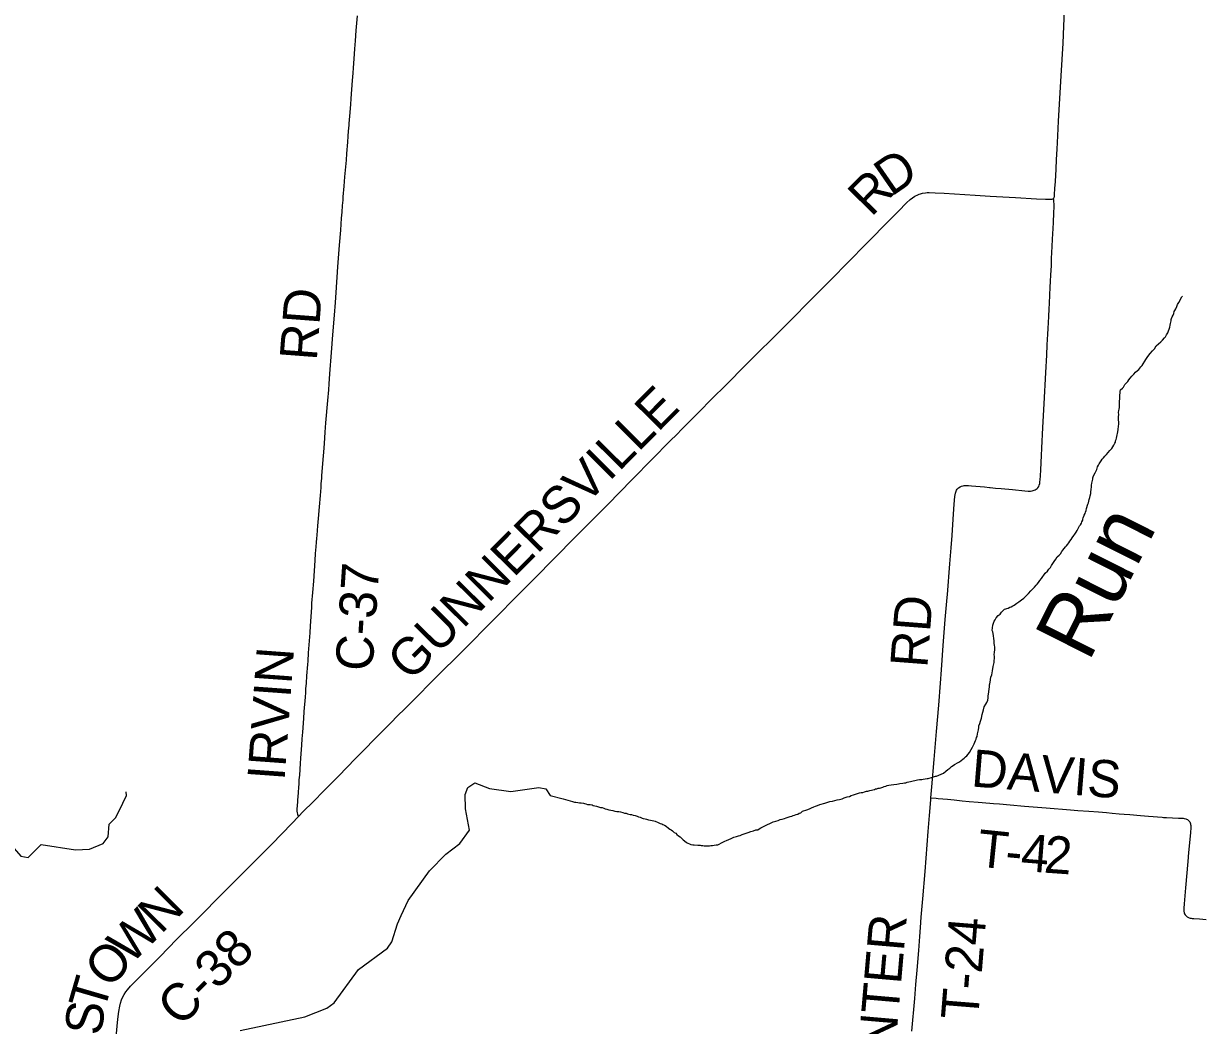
# Model space of a CAD drawing. Extents: x -49 to -8.2, y 9.4 to 23.5.
# Drawn here: x -45.157 to -44.259, y 16.399 to 17.164 of the extents above; entities that cross this region are included whole.
import ezdxf

# ---------------------------------------------------------------- set-up
doc = ezdxf.new("R2010")
doc.units = 0
for name, color, linetype in [('GM_X_County_Road', 7, 'Continuous'), ('GM_X_County_Road_Text', 7, 'Continuous'), ('GM_X_Minor_River', 7, 'Continuous'), ('GM_X_Minor_River_Text', 7, 'Continuous'), ('GM_X_Township_Road', 7, 'Continuous'), ('GM_X_Township_Road_Text', 7, 'Continuous')]:
    doc.layers.add(name, color=color, linetype=linetype)

msp = doc.modelspace()

# ---------------------------------------------------------------- linework, layer by layer
at = {"layer": 'GM_X_County_Road'}
for points in [[(-44.37073, 17.03015), (-44.37057, 17.03029), (-44.37036, 17.03061), (-44.37019, 17.03103), (-44.37007, 17.03142), (-44.36999, 17.03185), (-44.36994, 17.03249), (-44.36989, 17.03307), (-44.36958, 17.03784), (-44.36928, 17.04311), (-44.36878, 17.05241), (-44.36842, 17.05986), (-44.36804, 17.06761), (-44.36754, 17.07785), (-44.36692, 17.08902), (-44.3664, 17.0977), (-44.36497, 17.12376), (-44.36345, 17.14857), (-44.36281, 17.1616), (-44.36196, 17.17898)], [(-44.94677, 16.55865), (-44.94719, 16.56018), (-44.94762, 16.56178), (-44.94776, 16.56239), (-44.94784, 16.56312), (-44.94776, 16.56478), (-44.94763, 16.5665), (-44.9473, 16.57047), (-44.94697, 16.57478), (-44.94686, 16.57601), (-44.9468, 16.57724), (-44.94655, 16.58094), (-44.94631, 16.58372), (-44.94612, 16.58682), (-44.94582, 16.59022), (-44.94521, 16.59921), (-44.94492, 16.60323), (-44.94413, 16.61314), (-44.94382, 16.6181), (-44.94342, 16.62306), (-44.94272, 16.6336), (-44.94232, 16.63886), (-44.94147, 16.6497), (-44.94121, 16.65341), (-44.94103, 16.6562), (-44.94066, 16.66053), (-44.94026, 16.6661), (-44.9396, 16.67477), (-44.93942, 16.67724), (-44.93903, 16.68348), (-44.93794, 16.69892), (-44.93758, 16.70425), (-44.93669, 16.71816), (-44.93645, 16.72157), (-44.93583, 16.72962), (-44.93513, 16.73829), (-44.93401, 16.75409), (-44.93368, 16.75936), (-44.93348, 16.76184), (-44.93326, 16.76431), (-44.93298, 16.76803), (-44.93273, 16.77081), (-44.93255, 16.77328), (-44.93196, 16.7804), (-44.93153, 16.78595), (-44.9308, 16.79493), (-44.93005, 16.8036), (-44.92981, 16.80669), (-44.92954, 16.80979), (-44.92936, 16.81257), (-44.92903, 16.81691), (-44.92895, 16.81845), (-44.92794, 16.83115), (-44.92752, 16.83673), (-44.92701, 16.84323), (-44.92629, 16.8519), (-44.92577, 16.85903), (-44.92439, 16.87606), (-44.92369, 16.88411), (-44.92331, 16.88875), (-44.92273, 16.89649), (-44.92153, 16.9126), (-44.92046, 16.92623), (-44.91933, 16.9411), (-44.91858, 16.9507), (-44.91798, 16.95845), (-44.91663, 16.97797), (-44.9154, 16.9944), (-44.91453, 17.00586), (-44.91422, 17.0105), (-44.91387, 17.01515), (-44.91351, 17.0198), (-44.9131, 17.02475), (-44.91278, 17.02877), (-44.91259, 17.03125), (-44.9119, 17.03961), (-44.91131, 17.04672), (-44.91023, 17.05941), (-44.90986, 17.06437), (-44.90918, 17.07304), (-44.90887, 17.07769), (-44.90855, 17.0814), (-44.9082, 17.08604), (-44.90809, 17.08728), (-44.90755, 17.09285), (-44.90682, 17.10183), (-44.90649, 17.10647), (-44.90544, 17.1201), (-44.90507, 17.12568), (-44.90477, 17.12971), (-44.90428, 17.13653), (-44.90369, 17.14428), (-44.90321, 17.15047), (-44.90265, 17.15822), (-44.90178, 17.1695)], [(-44.63127, 16.8772), (-44.62054, 16.88797), (-44.60569, 16.90299), (-44.57555, 16.93305), (-44.55189, 16.95684), (-44.53895, 16.96983), (-44.5289, 16.97999), (-44.51186, 16.99722), (-44.4971, 17.01233), (-44.48907, 17.02056), (-44.48292, 17.02675), (-44.48012, 17.02927), (-44.47838, 17.03062), (-44.47653, 17.03183), (-44.47427, 17.03299), (-44.47318, 17.03342), (-44.47219, 17.03376), (-44.47065, 17.03417), (-44.46845, 17.03454), (-44.46712, 17.03465), (-44.46561, 17.03465), (-44.46092, 17.03442), (-44.4541, 17.03408), (-44.43053, 17.03266), (-44.41906, 17.03199), (-44.39982, 17.03086), (-44.38363, 17.02988), (-44.37689, 17.0296), (-44.37259, 17.02961), (-44.37221, 17.02963), (-44.3717, 17.02969), (-44.3713, 17.02983), (-44.37084, 17.03005), (-44.37073, 17.03015)], [(-44.94677, 16.55865), (-44.94308, 16.56245), (-44.93563, 16.56995), (-44.92712, 16.57856), (-44.92255, 16.58322), (-44.91601, 16.58986), (-44.90992, 16.59607), (-44.90319, 16.60296), (-44.89751, 16.60871), (-44.88768, 16.61865), (-44.88095, 16.62553), (-44.87658, 16.62995), (-44.87091, 16.6357), (-44.86583, 16.64073), (-44.86273, 16.64378), (-44.85811, 16.64839), (-44.85373, 16.65278), (-44.84825, 16.6583), (-44.83556, 16.67109), (-44.82807, 16.67854), (-44.81358, 16.69304), (-44.80571, 16.70099), (-44.79631, 16.71049), (-44.79171, 16.71511), (-44.78469, 16.72215), (-44.77597, 16.731), (-44.76896, 16.73806), (-44.74908, 16.75816), (-44.73796, 16.76944), (-44.72966, 16.77784), (-44.72242, 16.78511), (-44.7108, 16.79677), (-44.69232, 16.81564), (-44.67648, 16.83188), (-44.66395, 16.84439), (-44.65737, 16.85098), (-44.65495, 16.8534), (-44.64137, 16.86706), (-44.63127, 16.8772)], [(-45.08591, 16.39077), (-45.08462, 16.40408), (-45.08387, 16.40995), (-45.08314, 16.41395), (-45.08251, 16.41639), (-45.08171, 16.41878), (-45.0807, 16.4211), (-45.07967, 16.42305), (-45.07847, 16.42492), (-45.07712, 16.42666), (-45.07481, 16.42922), (-45.06742, 16.4368), (-45.05247, 16.45172), (-45.03947, 16.46507), (-45.02698, 16.47764), (-45.01817, 16.4864), (-45.00944, 16.49524), (-45.00179, 16.50297), (-44.98725, 16.51743), (-44.96716, 16.53776), (-44.95195, 16.55331), (-44.94677, 16.55865)]]:
    msp.add_lwpolyline(points, dxfattribs=at)
at = {"layer": 'GM_X_Minor_River'}
for points in [[(-44.3141, 16.8906), (-44.31332, 16.89173), (-44.31234, 16.89304), (-44.31098, 16.89454), (-44.30942, 16.89623), (-44.30806, 16.89753), (-44.30652, 16.89884), (-44.30555, 16.89958), (-44.30477, 16.90071), (-44.30398, 16.90183), (-44.3032, 16.90277), (-44.30026, 16.90728), (-44.2987, 16.90954), (-44.29694, 16.91179), (-44.29519, 16.91385), (-44.29363, 16.91554), (-44.29245, 16.91761), (-44.29051, 16.91928), (-44.28896, 16.92078), (-44.2876, 16.92209), (-44.28605, 16.92377), (-44.28527, 16.92471), (-44.28448, 16.92602), (-44.2835, 16.92753), (-44.28309, 16.92904), (-44.28249, 16.93056), (-44.28208, 16.93188), (-44.28168, 16.9334), (-44.28146, 16.93472), (-44.28125, 16.93567), (-44.28085, 16.9368), (-44.28083, 16.93776), (-44.28062, 16.9387), (-44.28022, 16.93984), (-44.27944, 16.94116), (-44.27884, 16.94248), (-44.27862, 16.94381), (-44.27804, 16.94475), (-44.27744, 16.94607), (-44.27665, 16.94776), (-44.27605, 16.94928), (-44.27507, 16.95078), (-44.27289, 16.95512), (-44.27231, 16.95568), (-44.27231, 16.95549)], [(-44.36783, 16.75686), (-44.36647, 16.75816), (-44.3655, 16.7591), (-44.36432, 16.76098), (-44.36354, 16.76191), (-44.36257, 16.76304), (-44.36159, 16.76435), (-44.36081, 16.76529), (-44.35984, 16.76641), (-44.35905, 16.76754), (-44.35827, 16.76886), (-44.35729, 16.76998), (-44.35651, 16.7713), (-44.35533, 16.77299), (-44.35436, 16.77412), (-44.35338, 16.77562), (-44.35278, 16.77694), (-44.3518, 16.77845), (-44.35081, 16.78033), (-44.35003, 16.78127), (-44.34944, 16.78259), (-44.34904, 16.78353), (-44.34845, 16.78466), (-44.34824, 16.78561), (-44.34803, 16.78656), (-44.34763, 16.78769), (-44.34742, 16.78864), (-44.34664, 16.78996), (-44.34643, 16.79091), (-44.34583, 16.79223), (-44.34542, 16.79374), (-44.34441, 16.79696), (-44.34401, 16.7979), (-44.3438, 16.79923), (-44.34339, 16.80056), (-44.34298, 16.80207), (-44.34277, 16.8034), (-44.34235, 16.8051), (-44.34214, 16.80643), (-44.34192, 16.80814), (-44.34169, 16.81023), (-44.34166, 16.81156), (-44.34145, 16.81289), (-44.34124, 16.81403), (-44.34103, 16.81498), (-44.34082, 16.81592), (-44.34061, 16.81706), (-44.3402, 16.81858), (-44.33883, 16.82084), (-44.33842, 16.82197), (-44.33763, 16.82348), (-44.33742, 16.82442), (-44.33703, 16.82537), (-44.33643, 16.82669), (-44.33584, 16.82763), (-44.33544, 16.82857), (-44.33428, 16.82989), (-44.33348, 16.83139), (-44.33251, 16.83233), (-44.33154, 16.83364), (-44.33037, 16.83495), (-44.32901, 16.83626), (-44.32765, 16.83795), (-44.32628, 16.83944), (-44.3255, 16.84057), (-44.32471, 16.84208), (-44.32392, 16.8434), (-44.32334, 16.84434), (-44.32332, 16.84529), (-44.32292, 16.84623), (-44.32271, 16.84718), (-44.32231, 16.84851), (-44.32209, 16.84983), (-44.32188, 16.85078), (-44.32126, 16.85362), (-44.32143, 16.85458), (-44.32103, 16.85571), (-44.3212, 16.85667), (-44.32099, 16.85781), (-44.32077, 16.85932), (-44.32112, 16.86142), (-44.32108, 16.86352), (-44.32085, 16.86542), (-44.32101, 16.86694), (-44.3208, 16.86846), (-44.32059, 16.86941), (-44.32037, 16.87073), (-44.32035, 16.87207), (-44.32032, 16.87359), (-44.32029, 16.87549), (-44.32006, 16.87739), (-44.32022, 16.87892), (-44.32001, 16.88024), (-44.31998, 16.88158), (-44.31996, 16.88291), (-44.31956, 16.88404), (-44.3182, 16.88535), (-44.31742, 16.88629), (-44.31624, 16.88817), (-44.31488, 16.88966), (-44.3141, 16.8906)], [(-44.44621, 16.59844), (-44.44352, 16.59991), (-44.44255, 16.60047), (-44.43985, 16.60251), (-44.43888, 16.60325), (-44.43791, 16.60419), (-44.43694, 16.60512), (-44.43578, 16.60624), (-44.4348, 16.60756), (-44.43342, 16.60981), (-44.43263, 16.61151), (-44.43184, 16.61302), (-44.43125, 16.61415), (-44.43065, 16.61547), (-44.43025, 16.6168), (-44.42985, 16.61774), (-44.42945, 16.61888), (-44.42905, 16.61982), (-44.42863, 16.62172), (-44.42821, 16.6238), (-44.428, 16.62494), (-44.42778, 16.62665), (-44.42757, 16.62779), (-44.42696, 16.62968), (-44.42636, 16.63138), (-44.42615, 16.63233), (-44.42574, 16.63384), (-44.42512, 16.6365), (-44.42471, 16.6382), (-44.4241, 16.64009), (-44.42368, 16.64237), (-44.42231, 16.64444), (-44.42152, 16.64575), (-44.42092, 16.64745), (-44.4205, 16.64916), (-44.42048, 16.65049), (-44.42004, 16.65391), (-44.4198, 16.65619), (-44.41959, 16.65733), (-44.41956, 16.65904), (-44.41935, 16.65999), (-44.41914, 16.66113), (-44.41849, 16.66511), (-44.4177, 16.66681), (-44.41726, 16.66984), (-44.41663, 16.67326), (-44.41621, 16.67515), (-44.41601, 16.6761), (-44.41598, 16.67762), (-44.41576, 16.67914), (-44.41573, 16.68066), (-44.41589, 16.68219), (-44.41567, 16.6839), (-44.41544, 16.68599), (-44.4156, 16.68789), (-44.41576, 16.68942), (-44.41593, 16.69075), (-44.41589, 16.69266), (-44.41624, 16.69457), (-44.41658, 16.69647), (-44.41674, 16.69819), (-44.4171, 16.69953), (-44.41746, 16.70068), (-44.41701, 16.70466), (-44.4166, 16.70618), (-44.416, 16.70769), (-44.41522, 16.70863), (-44.41443, 16.71014), (-44.41287, 16.71201), (-44.41151, 16.71313), (-44.41034, 16.71463), (-44.40821, 16.71687), (-44.40533, 16.71758), (-44.40399, 16.71832), (-44.40303, 16.71868), (-44.40187, 16.71942), (-44.40072, 16.71997), (-44.39975, 16.72071), (-44.39859, 16.72145), (-44.39705, 16.72257), (-44.39511, 16.72405), (-44.39338, 16.72516), (-44.39202, 16.72647), (-44.38988, 16.72872), (-44.38794, 16.73077), (-44.38639, 16.73227), (-44.38521, 16.73377), (-44.38386, 16.73507), (-44.38308, 16.73601), (-44.38229, 16.73714), (-44.38112, 16.73883), (-44.37995, 16.74014), (-44.37702, 16.74427), (-44.37527, 16.74595), (-44.37429, 16.74746), (-44.37312, 16.74877), (-44.37214, 16.75027), (-44.37116, 16.75178), (-44.37018, 16.75328), (-44.36901, 16.75497), (-44.36783, 16.75686)], [(-44.60364, 16.54653), (-44.60153, 16.54725), (-44.59962, 16.54779), (-44.59789, 16.54852), (-44.59636, 16.54868), (-44.5954, 16.54923), (-44.59405, 16.54997), (-44.5929, 16.55052), (-44.59193, 16.55107), (-44.59097, 16.55162), (-44.58982, 16.55217), (-44.58617, 16.55382), (-44.58463, 16.55455), (-44.58252, 16.55528), (-44.58079, 16.55581), (-44.57926, 16.55636), (-44.57773, 16.55671), (-44.576, 16.55725), (-44.57466, 16.5578), (-44.57312, 16.55834), (-44.57159, 16.55869), (-44.57025, 16.55905), (-44.56929, 16.5596), (-44.56833, 16.55977), (-44.56699, 16.56032), (-44.56584, 16.56049), (-44.56468, 16.56123), (-44.56353, 16.56159), (-44.56217, 16.56289), (-44.55892, 16.56379), (-44.557, 16.56451), (-44.55546, 16.56524), (-44.55354, 16.56616), (-44.55238, 16.56671), (-44.55066, 16.56725), (-44.54912, 16.56779), (-44.54797, 16.56815), (-44.54625, 16.56869), (-44.5451, 16.56886), (-44.54127, 16.57012), (-44.53936, 16.57047), (-44.53744, 16.571), (-44.53572, 16.57135), (-44.534, 16.5717), (-44.53208, 16.57224), (-44.53035, 16.57297), (-44.52824, 16.57369), (-44.52633, 16.57403), (-44.52498, 16.57477), (-44.52326, 16.57531), (-44.52173, 16.57566), (-44.52019, 16.5762), (-44.51866, 16.57675), (-44.51751, 16.57692), (-44.51617, 16.57708), (-44.51502, 16.57744), (-44.5133, 16.57798), (-44.51234, 16.57815), (-44.51081, 16.57851), (-44.50966, 16.57886), (-44.50851, 16.57903), (-44.50736, 16.57939), (-44.5064, 16.57976), (-44.50545, 16.57993), (-44.50449, 16.58029), (-44.50353, 16.58047), (-44.50257, 16.58064), (-44.50104, 16.58118), (-44.49989, 16.58154), (-44.49874, 16.5819), (-44.49759, 16.58226), (-44.49625, 16.58261), (-44.49453, 16.58296), (-44.49243, 16.58312), (-44.49032, 16.58346), (-44.48899, 16.58362), (-44.48784, 16.58379), (-44.48555, 16.58413), (-44.4844, 16.58449), (-44.48344, 16.58447), (-44.48249, 16.58484), (-44.48114, 16.58519), (-44.47981, 16.58536), (-44.47445, 16.58659), (-44.47292, 16.58694), (-44.4712, 16.58691), (-44.47005, 16.58727), (-44.46852, 16.58743), (-44.46719, 16.5876), (-44.46623, 16.58777), (-44.46297, 16.58885), (-44.46086, 16.58939), (-44.45991, 16.58956), (-44.45645, 16.59102), (-44.45453, 16.59174), (-44.45298, 16.59324), (-44.45124, 16.59454), (-44.44989, 16.59565), (-44.44853, 16.59696), (-44.44718, 16.5977), (-44.44621, 16.59844)], [(-45.3102, 16.50634), (-45.28797, 16.50902), (-45.26909, 16.51751), (-45.22624, 16.53195), (-45.1846, 16.54109), (-45.16718, 16.5384), (-45.15858, 16.52842), (-45.15309, 16.5274), (-45.14311, 16.53733), (-45.11698, 16.53338), (-45.10617, 16.53381), (-45.09588, 16.53805), (-45.09202, 16.54312), (-45.09115, 16.55298), (-45.08616, 16.55785), (-45.08071, 16.56898), (-45.07799, 16.57464), (-45.07815, 16.57749)], [(-44.99137, 16.39547), (-44.94194, 16.40584), (-44.92517, 16.41246), (-44.91943, 16.41656), (-44.90092, 16.44195), (-44.87873, 16.45836), (-44.87544, 16.46325), (-44.87111, 16.47686), (-44.86837, 16.48328), (-44.86312, 16.49479), (-44.84673, 16.51736), (-44.83444, 16.53011), (-44.82372, 16.53813), (-44.8162, 16.54828), (-44.81942, 16.56465), (-44.81948, 16.57547), (-44.81752, 16.58095), (-44.81217, 16.58429), (-44.80103, 16.57997), (-44.78474, 16.57786), (-44.76328, 16.58081), (-44.75798, 16.5798), (-44.75482, 16.57482), (-44.74482, 16.57217)], [(-44.74482, 16.57217), (-44.73777, 16.57012), (-44.73606, 16.56971), (-44.73511, 16.56969), (-44.73359, 16.56947), (-44.73226, 16.56926), (-44.73112, 16.56905), (-44.72941, 16.56882), (-44.72846, 16.56862), (-44.72751, 16.56841), (-44.72618, 16.568), (-44.72523, 16.56799), (-44.72428, 16.56778), (-44.72276, 16.56756), (-44.72181, 16.56716), (-44.72067, 16.56695), (-44.71935, 16.56655), (-44.71631, 16.56573), (-44.71517, 16.56552), (-44.71385, 16.56511), (-44.71271, 16.56471), (-44.71138, 16.56431), (-44.70987, 16.5639), (-44.70854, 16.56349), (-44.70702, 16.56327), (-44.7055, 16.56287), (-44.70379, 16.56264), (-44.70227, 16.56243), (-44.70113, 16.56221), (-44.69923, 16.5618), (-44.69809, 16.5614), (-44.69676, 16.56118), (-44.69563, 16.56078), (-44.69468, 16.56057), (-44.69373, 16.56037), (-44.69259, 16.56015), (-44.69145, 16.55975), (-44.68993, 16.55953), (-44.68842, 16.55894), (-44.68728, 16.55853), (-44.68595, 16.55832), (-44.68463, 16.55753), (-44.68368, 16.55733), (-44.68217, 16.55692), (-44.68122, 16.55671), (-44.6797, 16.5563), (-44.67818, 16.55589), (-44.67704, 16.55568), (-44.67571, 16.55547), (-44.67458, 16.55507), (-44.67231, 16.55426), (-44.6708, 16.55347), (-44.66966, 16.55307), (-44.66871, 16.55267), (-44.66739, 16.55208), (-44.66626, 16.5513), (-44.66438, 16.54993), (-44.66344, 16.54915), (-44.6625, 16.54856), (-44.66137, 16.54778), (-44.66006, 16.54661), (-44.65892, 16.54602), (-44.65799, 16.54505), (-44.65687, 16.54389), (-44.65555, 16.54311), (-44.65461, 16.54214), (-44.6533, 16.54097), (-44.65236, 16.54019), (-44.65067, 16.53883), (-44.64973, 16.53843), (-44.6484, 16.53784), (-44.64746, 16.53744), (-44.64594, 16.53722), (-44.64479, 16.5372), (-44.64213, 16.53696), (-44.64041, 16.53693), (-44.63946, 16.53672), (-44.63832, 16.53651), (-44.63737, 16.53649), (-44.63642, 16.53647), (-44.63432, 16.53644), (-44.63318, 16.53641), (-44.63222, 16.53659), (-44.63089, 16.53656), (-44.62955, 16.53692), (-44.62802, 16.53708), (-44.62688, 16.53725), (-44.62573, 16.53761), (-44.62399, 16.53872), (-44.62245, 16.53945), (-44.62149, 16.54001), (-44.62014, 16.54055), (-44.61669, 16.54201), (-44.61457, 16.54292), (-44.61247, 16.54346), (-44.61112, 16.544), (-44.60978, 16.54436), (-44.60825, 16.5449), (-44.60671, 16.54544), (-44.60518, 16.54599), (-44.60364, 16.54653)]]:
    msp.add_lwpolyline(points, dxfattribs=at)
at = {"layer": 'GM_X_Township_Road'}
for points in [[(-44.38959, 16.80697), (-44.38921, 16.80695), (-44.38832, 16.80697), (-44.38706, 16.80708), (-44.38617, 16.80728), (-44.38537, 16.80754), (-44.38474, 16.80785), (-44.38396, 16.80829), (-44.38318, 16.80889), (-44.38259, 16.80952), (-44.38196, 16.81053), (-44.3816, 16.81146), (-44.38123, 16.81263), (-44.38108, 16.81399), (-44.38091, 16.81542), (-44.3807, 16.81858), (-44.38048, 16.82319), (-44.37997, 16.83404), (-44.37972, 16.83963), (-44.37884, 16.85545), (-44.37789, 16.87344), (-44.37661, 16.89733), (-44.3759, 16.91067), (-44.37547, 16.9185), (-44.37497, 16.92659), (-44.37471, 16.93101), (-44.37422, 16.94011), (-44.37394, 16.94601), (-44.37375, 16.95004), (-44.37345, 16.95667), (-44.37324, 16.96211), (-44.37297, 16.9671), (-44.37268, 16.97175), (-44.37235, 16.97909), (-44.37214, 16.98416), (-44.37201, 16.98917), (-44.3718, 16.99315), (-44.37151, 16.99936), (-44.37134, 17.00286), (-44.37109, 17.00737), (-44.37084, 17.01154), (-44.37036, 17.0195), (-44.3702, 17.02353), (-44.37022, 17.02583), (-44.37039, 17.02774), (-44.37057, 17.02898), (-44.37073, 17.03015)], [(-44.4517, 16.72806), (-44.44987, 16.75139), (-44.4488, 16.76377), (-44.44809, 16.77306), (-44.44729, 16.78547), (-44.44642, 16.79693), (-44.44602, 16.80284), (-44.4458, 16.80413), (-44.4456, 16.80528), (-44.44534, 16.80615), (-44.44504, 16.80691), (-44.44471, 16.80754), (-44.4442, 16.8083), (-44.44374, 16.80889), (-44.44315, 16.80939), (-44.44202, 16.81011), (-44.44089, 16.81061), (-44.43971, 16.81096), (-44.43881, 16.81113), (-44.43785, 16.81122), (-44.43567, 16.81121), (-44.43318, 16.81104), (-44.42329, 16.81011), (-44.41958, 16.80979), (-44.41896, 16.80968), (-44.41494, 16.80929), (-44.41074, 16.80889), (-44.40196, 16.80808), (-44.39267, 16.80716), (-44.39017, 16.80699), (-44.38959, 16.80697)], [(-44.46419, 16.57306), (-44.46347, 16.5814), (-44.4617, 16.60214), (-44.45994, 16.62349), (-44.45833, 16.64362), (-44.45703, 16.66035), (-44.45628, 16.67057), (-44.45479, 16.68915), (-44.45329, 16.70897), (-44.45189, 16.72569), (-44.4517, 16.72806)], [(-44.47879, 16.39505), (-44.47661, 16.4198), (-44.47576, 16.43064), (-44.47483, 16.44147), (-44.47352, 16.45663), (-44.47275, 16.46717), (-44.47228, 16.47398), (-44.47164, 16.48203), (-44.47043, 16.49595), (-44.46872, 16.5167), (-44.46623, 16.54735), (-44.46532, 16.55943), (-44.46433, 16.5715), (-44.46419, 16.57306)], [(-44.46419, 16.57306), (-44.46016, 16.57268), (-44.45861, 16.57253), (-44.4515, 16.57184), (-44.44656, 16.57136), (-44.44037, 16.57081), (-44.43512, 16.57029), (-44.42832, 16.56968), (-44.42522, 16.56946), (-44.41657, 16.56878), (-44.41194, 16.56832), (-44.4039, 16.56756), (-44.39276, 16.56659), (-44.37635, 16.56525), (-44.35778, 16.56383), (-44.3522, 16.56341), (-44.34384, 16.56283), (-44.33642, 16.56221), (-44.33023, 16.5617), (-44.3259, 16.56132), (-44.32074, 16.56086)], [(-44.32074, 16.56086), (-44.31693, 16.56052), (-44.3126, 16.56015), (-44.30425, 16.55939), (-44.29837, 16.55889), (-44.28783, 16.55817), (-44.28691, 16.55808), (-44.28443, 16.55793), (-44.27546, 16.55758), (-44.27168, 16.5574), (-44.27092, 16.55727), (-44.26986, 16.557), (-44.26914, 16.55673), (-44.26847, 16.55634), (-44.26799, 16.55598), (-44.26761, 16.55561), (-44.26714, 16.55509), (-44.26683, 16.55461), (-44.26654, 16.55401), (-44.26626, 16.55314), (-44.26614, 16.55257), (-44.26604, 16.55191), (-44.26599, 16.55119), (-44.26599, 16.55035), (-44.26631, 16.54632), (-44.26764, 16.53116), (-44.26819, 16.52434), (-44.26997, 16.50423), (-44.27105, 16.49216), (-44.27131, 16.48874), (-44.2713, 16.48759), (-44.27124, 16.48656), (-44.27096, 16.48536), (-44.27066, 16.48451), (-44.2703, 16.48381), (-44.26984, 16.4832), (-44.2693, 16.4827), (-44.26867, 16.48222), (-44.26815, 16.4819), (-44.26718, 16.48146), (-44.26645, 16.48123), (-44.2658, 16.48112), (-44.26495, 16.48096), (-44.26363, 16.48085), (-44.25927, 16.48063), (-44.25412, 16.48027)]]:
    msp.add_lwpolyline(points, dxfattribs=at)

# ---------------------------------------------------------------- texts
at = {"layer": 'GM_X_County_Road_Text'}
for s, height, rotation, p in [('D', 0.02841, 34.63479, (-44.49453, 17.03114)), ('R', 0.02841, 45.52163, (-44.50978, 17.01541)), ('RD', 0.028409, 85.66763, (-44.93285, 16.90597)), ('GUNNERSVILLE', 0.0284091, 45.24835, (-44.86132, 16.66097)), ('C-37', 0.028409, 86.23141, (-44.89037, 16.66904)), ('IRVIN', 0.028409, 85.86221, (-44.95743, 16.58565)), ('N', 0.02841, 45.20993, (-45.05161, 16.46839)), ('W', 0.02841, 45.23378, (-45.07478, 16.44502)), ('C-38', 0.028409, 45.23814, (-45.03683, 16.39734)), ('O', 0.02841, 49.18692, (-45.09077, 16.42648)), ('T', 0.02841, 73.76379, (-45.09519, 16.40888)), ('S', 0.02841, 83.55775, (-45.09708, 16.39109))]:
    msp.add_text(s, height=height, rotation=rotation, dxfattribs=at).set_placement(p)
at = {"layer": 'GM_X_Minor_River_Text'}
msp.add_text('Run', height=0.047343, rotation=63.21074, dxfattribs=at).set_placement((-44.34399, 16.67575))
at = {"layer": 'GM_X_Township_Road_Text'}
for s, height, rotation, p in [('RD', 0.028409, 85.60093, (-44.46703, 16.6717)), ('DAVIS', 0.028409, 355.32807, (-44.43404, 16.58172)), ('T', 0.02841, 354.11201, (-44.42977, 16.52072)), ('4', 0.02841, 355.43814, (-44.3963, 16.51742)), ('2', 0.02841, 355.96894, (-44.37857, 16.516)), ('-', 0.02841, 354.81158, (-44.40826, 16.5185)), ('CARPENTER', 0.028409, 85.02509, (-44.50285, 16.24944)), ('T-24', 0.028409, 85.41062, (-44.42836, 16.40295))]:
    msp.add_text(s, height=height, rotation=rotation, dxfattribs=at).set_placement(p)

doc.saveas('drawing.dxf')
